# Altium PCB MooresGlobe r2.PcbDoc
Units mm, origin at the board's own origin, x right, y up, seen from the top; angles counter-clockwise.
Board outline 12 x 11 mm, 2 copper layers (Top Layer, Bottom Layer), stack 0.801 mm thick; 9 components, 5 nets, 22 pads, 2 vias.
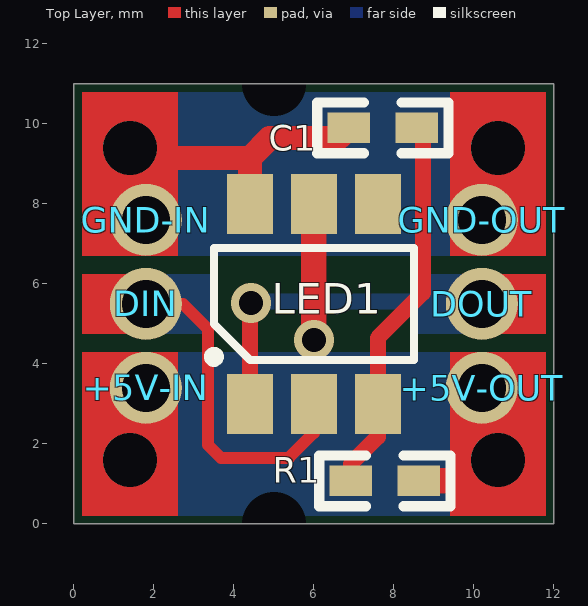
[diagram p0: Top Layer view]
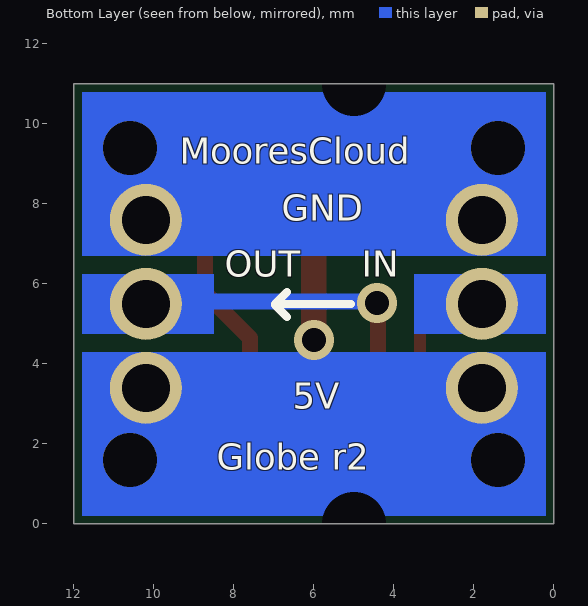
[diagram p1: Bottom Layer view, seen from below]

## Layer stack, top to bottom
Top Layer: signal copper 0.0356
Dielectric: core 0.73, FR-4, Dk 4.8
Bottom Layer: signal copper 0.0356

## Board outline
0,0 12,0 12,11 0,11

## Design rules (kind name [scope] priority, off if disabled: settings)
Clearance [All] p1: gap=0.254
HoleSize [All] p1: absolutevalues=TRUE maxlimit=3 minlimit=0.3 maxpercent=80.000 minpercent=20.000
MinimumSolderMaskSliver [All] p1: minsoldermaskwidth=0.152
PlaneClearance [All] p1: clearance=0.254
PolygonConnect [All] p1: connectstyle=Direct reliefconductorwidth=1.5 reliefentries=4 polygonreliefangle="90 Angle" airgapwidth=0.254
RoutingVias [All] p1: holewidth=0.4 width=0.6 viastyle="Through Hole" minholewidth=0.3 minwidth=0.6 maxholewidth=1 maxwidth=1.27
SilkToSilkClearance [All] p1 off: silktosilkclearance=0
SilkToSolderMaskClearance [IsPad] p1: minsilkscreentomaskgap=0.102 clearancetoexposedcopper=TRUE
SolderMaskExpansion [All] p1: expansion=0.102
Width [All] p1: maxlimit=1.27 minlimit=0.254 preferedwidth=0.254 minimp=50.000000 maximp=50.000000 favimp=50.000000
23 further rules are at their usual default settings.

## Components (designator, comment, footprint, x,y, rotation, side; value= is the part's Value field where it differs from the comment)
+5V-IN "+5V" "Solder Pad"#1 -2.3,1.7 r90 top
+5V-OUT "+5V" "Solder Pad"#2 14.027,2.326 r90 top
C1 "100n" ARA_0603 8.575,9.9 r180 top
DIN "DIN" "Solder Pad"#3 -1.95,5.525 r90 top
DOUT "DOUT" "Solder Pad"#4 10.2,5.475 r90 top
GND-IN "GND" "Solder Pad"#5 -1.85,9.2 r90 top
GND-OUT "GND" "Solder Pad"#6 10.2,8.925 r90 top
LED1 "WS2812" PLCC6-IPC 6,5.5 r90 top locked
R1 "100R" ARA_0603 8.625,1.075 r180 top

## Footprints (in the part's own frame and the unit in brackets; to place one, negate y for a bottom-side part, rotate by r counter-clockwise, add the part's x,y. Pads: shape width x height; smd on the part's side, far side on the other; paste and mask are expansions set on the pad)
ARA_0603 [mil]
  rect 42x30 smd: 1(0,0) 2(66.91,0)
  silkscreen extent -31,-25 98,25, body extent 0,-16 67,16, height 20
PLCC6-IPC [mm] "Leaded Chip Carrier, 12-Leads, Body 9.90x5.40mm, Pitch 1.600mm, IPC Medium Density"
  rect 1.5x1.15 smd: 1(-2.5,1.6) 2(-2.5,0) 3(-2.5,-1.6) 4(2.5,-1.6) 5(2.5,0) 6(2.5,1.6)
  silkscreen extent -1.45,-2.5 1.4,2.62, body extent -2.5,-2.5 2.5,2.5, height 1.61
"Solder Pad"#1 [mm]
  round 1.8 hole 1.2: 1(1.7,-4.1)
"Solder Pad"#2 [mm]
  round 1.8 hole 1.2: 1(1.074,3.827)
"Solder Pad"#3 [mm]
  round 1.8 hole 1.2: 1(-0.025,-3.75)
"Solder Pad"#4 [mm]
  round 1.8 hole 1.2: 1(0.025,0)
"Solder Pad"#5 [mm]
  round 1.8 hole 1.2: 1(-1.6,-3.65)
"Solder Pad"#6 [mm]
  round 1.8 hole 1.2: 1(-1.325,0)

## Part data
+5V-IN +5V-OUT DIN DOUT GND-IN GND-OUT: library part "Solder Pad", "Solder pad"
C1: library part CAP, "Capacitor Ceramic 100n 50V Y5V 0603"
LED1: "WorldSemi WS2812 Smart RGB LED"
R1: library part "Res Semi", "Resistor 100R 0.1W 5% 0603"

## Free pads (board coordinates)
  round 1.35 hole 1.35: 0(1.4,1.6) 0(1.4,9.4) 0(10.6,1.6) 0(10.6,9.4)
  round 0 hole 1.6 unplated: 0(5,0) 0(5,11)

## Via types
v1: diameter 1, hole 0.6, Top Layer to Bottom Layer, tented both sides, 2 vias

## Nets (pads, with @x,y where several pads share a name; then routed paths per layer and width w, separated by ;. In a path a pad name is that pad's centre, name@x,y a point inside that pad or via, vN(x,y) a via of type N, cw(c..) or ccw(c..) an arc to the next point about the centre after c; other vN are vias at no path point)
5V: +5V-IN.1 +5V-OUT.1 LED1.5 pad.0@1.4,1.6 pad.0@5,0 pad.0@10.6,1.6 R1.1 | length 10.2
  Top Layer w0.635: v1(6,4.6) LED1.5 ; R1.1 9.7,1.075 ; +5V-OUT.1@9.85,3.05 +5V-OUT.1
  Bottom Layer w0.635: +5V-IN.1 5.725,3.4 6,3.675 v1(6,4.6)
DIN: DIN.1 LED1.2 | length 8.5
  Top Layer w0.3: DIN.1 2.725,5.5 3.35,4.875 3.35,1.975 3.675,1.65 5.375,1.65 6,2.275 LED1.2
DOUT: DOUT.1 LED1.1 | length 8.3
  Top Layer w0.4: LED1.1 v1@4.4,5.525
  Bottom Layer w0.4: v1(4.425,5.525) 4.454,5.554 10.146,5.554 DOUT.1
GND: C1.2 GND-IN.1 GND-OUT.1 LED1.6 pad.0@1.4,9.4 pad.0@5,11 pad.0@10.6,9.4 | length 6.1
  Top Layer w0.6: 2.275,9.15 4.4,9.15 ; LED1.6 4.4,9.15 ; C1.2 6.621,9.646 4.896,9.646 4.4,9.15
NetC1_1: C1.1 LED1.3 R1.2 | length 9.6
  Top Layer w0.4: R1.2 6.925,1.5 7.6,2.175 LED1.3 7.6,4.65 8.725,5.775 8.725,9.75 C1.1
pads on no net: LED1.4

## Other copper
Top Layer:
  rectangle net DOUT: 9.75,4.75 11.8,6.25
  rectangle net DIN: 0.2,4.75 2.25,6.25
  rectangle net 5V: 0.2,3 2.25,4
  rectangle net GND: 0.2,7 2.25,8
  rectangle net GND: 9.75,7 11.8,8
  rectangle net 5V: 9.75,3 11.8,4
  rectangle net GND: 0.2,6.7 2.6,10.8
  rectangle net 5V: 0.2,0.2 2.6,4.3
  rectangle net 5V: 9.4,0.2 11.8,4.3
  rectangle net GND: 9.4,6.7 11.8,10.8
Bottom Layer:
  rectangle net DOUT: 8.5,4.75 11.8,6.25
  rectangle net DIN: 0.2,4.75 3.5,6.25
  rectangle net 5V: 0.2,2.6 3.5,4.1
  rectangle net GND: 0.2,6.9 3.5,8.4
  rectangle net GND: 8.5,6.9 11.8,8.4
  rectangle net 5V: 8.5,2.6 11.8,4.1
  rectangle net GND: 0.2,6.7 11.8,10.8
  rectangle net 5V: 0.2,0.2 11.8,4.3

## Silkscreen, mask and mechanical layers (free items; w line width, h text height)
Bottom Overlay:
  lines w0.203: 5.075,5.5 6.975,5.5 6.675,5.8 ; 6.675,5.175 6.975,5.475
  text "MooresCloud" at 9.35,9 h0.65
  text "GND" at 6.8,7.575 h0.65
  text "IN" at 4.8,6.175 h0.65
  text "OUT" at 8.225,6.175 h0.65
  text "5V" at 6.525,2.875 h0.65
  text "Globe r2" at 8.425,1.35 h0.65
Mechanical 1:
  the board outline again, w0.6
Mechanical 2:
  rectangle: 4.35,0 5.65,1.3
  rectangle: 4.35,9.7 5.65,11
  rectangle: 0,1.85 0.75,2.85
  rectangle: 0,8.15 0.75,9.15
  rectangle: 11.25,8.15 12,9.15
  rectangle: 11.25,1.85 12,2.85
  region: 0,11 0,10.4 2.2,11
  region: 0,0 0,0.6 2.2,0
  region: 12,0 12,0.6 9.8,0
  region: 12,11 12,10.4 9.8,11
  text "Top Layer Component Keep Out Areas" at 21,4 h1
Mechanical 3:
  rectangle: 9.5,0 12,0.7
  rectangle: 0,0 2.5,0.75
  rectangle: 0,10.25 2.5,11
  rectangle: 9.5,10.3 12,11
  rectangle: 5.25,10.25 6.75,11
  rectangle: 5.25,0 6.75,0.75
  text "Bottom Layer Component Keep Out Areas" at 21,2 h1
Drill Drawing:
  lines w0.1: 21,-3.25 79.25,-3.25 ; 21,-1.25 79.25,-1.25 ; 21,7.5 79.25,7.5 ; 21,9.5 79.25,9.5 ; 21,11.5 79.25,11.5 ; 21,13.5 79.25,13.5 ; 21,15.5 79.25,15.5 ; 21,17.5 79.25,17.5 ; 21,19.5 79.25,19.5 ; 21,21.5 79.25,21.5 ; 33.5,-5.25 33.5,1 ; 33.5,5.5 33.5,23.5 ; 0,0 12,0 12,11 0,11 0,0 ; 21,-5.25 79.25,-5.25 79.25,1 21,1 21,-5.25 ; 21,5.5 21,23.5 79.25,23.5 79.25,5.5 21,5.5
  text ".legend" at 22.25,28.75 h1
  text "BOARD SIZE:" at 21.5,22 h1
  text "12.00mm x 11.00mm" at 34.5,22 h1
  text "LAYERS:" at 21.5,20 h1
  text "2" at 34.5,20 h1
  text "MATERIAL:" at 21.5,18 h1
  text "FR4 0.8mm" at 34.5,18 h1
  text "COPPER:" at 21.5,16 h1
  text "35um (after plating)" at 34.5,16 h1
  text "PTH PLATING:" at 21.5,14 h1
  text "20um (minimum)" at 34.5,14 h1
  text "FINISH:" at 21.5,12 h1
  text "ROHS HAL" at 34.5,12 h1
  text "OVERLAY:" at 21.5,10 h1
  text "Black, 2 sides" at 34.5,10 h1
  text "SOLDER MASK:" at 21.5,8 h1
  text "White, 2 sides" at 34.5,8 h1
  text "PROFILING:" at 21.5,6 h1
  text "V-Groove" at 34.5,6 h1
  text "FILE NAME:" at 21.5,-0.75 h1
  text ".Pcb_File_Name_No_Path" at 34.5,-0.75 h1
  text "LAYER:" at 21.5,-2.75 h1
  text ".Plot_File_Name" at 34.5,-2.75 h1
  text "PRINT DATE:" at 21.5,-4.75 h1
  text ".Print_Date" at 34.5,-4.75 h1
Mechanical 20:
  the board outline again, w0.1

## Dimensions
-1,0 to -1,11 on Mechanical 16
0,-1 to 12,-1 on Mechanical 16
0,0 to 12,0 on Drill Drawing
0,0 to 0,11 on Drill Drawing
